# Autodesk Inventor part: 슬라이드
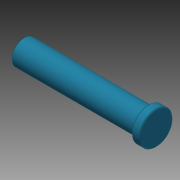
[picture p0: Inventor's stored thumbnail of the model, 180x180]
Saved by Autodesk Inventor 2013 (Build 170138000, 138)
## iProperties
Created: 2015-10
Part Number: 슬라이드
Document SubType Name: Modeling
Designer: mdu
Density: 7.86 g/cm^3
Material: 강철, 연강
Mass: 647.292 g
Surface Area: 163.597 cm^2
Volume: 82.3526 cm^3
Author: mdu
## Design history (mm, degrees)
sketch "스케치1"
  geometry: L1 (-75, 162)-(-75, 58) reference; L2 (-148, 110)-(12, 110); L3 (-148, 110)-(-148, 122.5); L4 (-148, 122.5)-(2, 122.5); L5 (2, 122.5)-(2, 130); L6 (2, 130)-(12, 130); L7 (12, 130)-(12, 110); 2 further points
  constraints: 12 end point, 3 parallel, 3 perpendicular, 1 midpoint, 1 point on line
  dimensions: "d0" = 40 diameter of L6 L2; "d1" = 25 diameter of L4 L2; "d2" = 10 distance of L5.end L6.end; "d3" = 160 distance of L2.start L2.end; "d4" = 73 distance between parallel lines of L3 L1
revolve "회전1" sketch "스케치1" stored, may be unused: angle "d5" = 90 deg
hole "구멍1" diameter "d11" = 13.376; stored, may be unused: countersink angle "d15" = 90 deg, drill point angle "d17" = 118 deg; dims "d9" = 10, "d10" = 10, "d12" = 22, "d13" = 4, "d14" = 2, "d16" = 25
chamfer "모따기1" distance "d6" = 1; stored, may be unused: second distance "d7" = 2, angle "d8" = 45 deg
node "솔리드1"
node "참조1"
